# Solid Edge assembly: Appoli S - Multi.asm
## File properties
Title: Appoli S - Multi
Author: petr.kostka
Keywords: ---
Template: Assembly Robe 03_24.asm
Last saved by: petr.kostka
Revision: 1221
Application: Solid Edge
Username: petr.kostka
Typ obsahu dokumentu: 1
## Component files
ek ramene.par
11X40268 Rameno Appoli S.psm
ka D=30mm.psm
ek Calumma.par
roub ramene Calumma.par
st Appoli S Anolis.par
r Appoli.psm
Housing Appoli S.par
r Calumma.psm
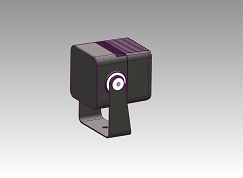
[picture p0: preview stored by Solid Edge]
